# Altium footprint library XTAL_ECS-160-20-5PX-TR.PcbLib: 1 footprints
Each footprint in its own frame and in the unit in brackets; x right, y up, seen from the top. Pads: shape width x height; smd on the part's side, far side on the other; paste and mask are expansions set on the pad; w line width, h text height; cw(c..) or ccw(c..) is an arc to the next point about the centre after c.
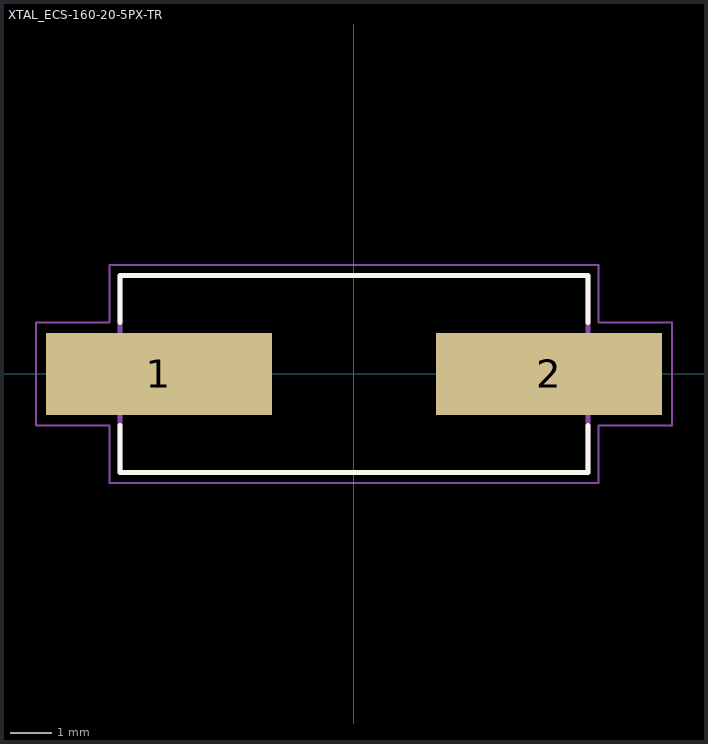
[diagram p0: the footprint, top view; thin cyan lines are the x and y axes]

## XTAL_ECS-160-20-5PX-TR [mm]
pads (2):
  rect 5.5x2 smd: 1(-4.75,0) 2(4.75,0)
Top Overlay:
  lines w0.127: -5.7,-1.254 -5.7,-2.4 5.7,-2.4 5.7,-1.254 ; -5.7,1.254 -5.7,2.4 5.7,2.4 5.7,1.254
Assembly Top:
  lines w0.127: -5.7,-2.4 -5.7,2.4 5.7,2.4 5.7,-2.4 -5.7,-2.4
Courtyard Top:
  lines w0.05: -7.75,-1.25 -5.95,-1.25 -5.95,-2.65 5.95,-2.65 5.95,-1.25 7.75,-1.25 7.75,1.25 5.95,1.25 5.95,2.65 -5.95,2.65 -5.95,1.25 -7.75,1.25 -7.75,-1.25
3D body "step_temp.STEP": height 3.2, standoff 0, extent -6.6,-2.4 6.6,2.4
